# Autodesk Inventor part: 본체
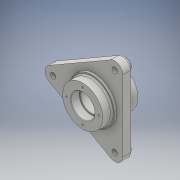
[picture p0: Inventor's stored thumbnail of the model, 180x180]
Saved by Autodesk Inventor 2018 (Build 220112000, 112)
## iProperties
Created: 2023-04
Part Number: 본체
Material: 일반
Document SubType Name: Modeling
Designer: home
Density: 1 g/cm^3
Appearance: 기본값
Author: home
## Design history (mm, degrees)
sketch "스케치1"
  geometry: L1 (82, 0)-(-41, -71.014); L2 (-41, -71.014)-(-41, 71.014); L3 (-41, 71.014)-(82, 0); L4 (90, 13.856)-(-33, 84.87); L5 (-57, 71.014)-(-57, -71.014); L6 (90, -13.856)-(-33, -84.87); A1 r 16 centre (82, 0) between (90, 13.856) and (90, -13.856); A2 r 16 centre (-41, 71.014) between (-33, 84.87) and (-57, 71.014); A3 r 16 centre (-41, -71.014) between (-57, -71.014) and (-33, -84.87); 2 further points
  constraints: 12 end point, 6 point on circle, 6 tangent, 3 centre point, 2 coincident, 1 vertical, 7 other
  dimensions: "d1" = 32 diameter of A1; "d2" = 32 diameter of A2; "d3" = 32 diameter of A3
extrude "돌출1" new body sketch "스케치1" distance "d4" = 18; taper "d5" = 0 deg
sketch "스케치3"
  geometry: L1 (-90, -13.856)-(33, -84.87) reference; L2 (57, -71.014)-(57, 71.014) reference; L3 (33, 84.87)-(-90, 13.856) reference; C1 r 11 at (41, -71.014); C2 r 11 at (41, 71.014); C3 r 11 at (-82, 0); A1 r 16 centre (41, -71.014) between (33, -84.87) and (57, -71.014) reference; A2 r 16 centre (41, 71.014) between (57, 71.014) and (33, 84.87) reference; A3 r 16 centre (-82, 0) between (-90, 13.856) and (-90, -13.856) reference; 1 further point
  constraints: 3 centre point, 3 coincident
  dimensions: "d8" = 22 diameter of C1; "d9" = 22 diameter of C2; "d10" = 22 diameter of C3
extrude "돌출2" join sketch "스케치3" distance "d11" = 4; taper "d12" = 0 deg
hole "구멍1" diameter "d15" = 11; stored, may be unused: countersink angle "d19" = 90 deg, drill point angle "d21" = 118 deg; dims "d13" = 10, "d14" = 10, "d16" = 6, "d17" = 4, "d18" = 2, "d20" = 8
hole "구멍2" diameter "d24" = 11; stored, may be unused: countersink angle "d28" = 90 deg, drill point angle "d30" = 118 deg; dims "d22" = 10, "d23" = 10, "d25" = 6, "d26" = 4, "d27" = 2, "d29" = 8
hole "구멍3" diameter "d33" = 11; stored, may be unused: countersink angle "d37" = 90 deg, drill point angle "d39" = 118 deg; dims "d31" = 10, "d32" = 10, "d34" = 6, "d35" = 4, "d36" = 2, "d38" = 8
sketch "스케치4"
  geometry: C1 r 40 at (0, 0); 1 further point
  constraints: 1 centre point, 1 coincident
  dimensions: "d40" = 80 diameter of C1
extrude "돌출3" join sketch "스케치4" distance "d41" = 29; taper "d42" = 0 deg
sketch "스케치5"
  geometry: C1 r 45 at (0, 0); 1 further point
  constraints: 1 centre point, 1 coincident
  dimensions: "d43" = 90 diameter of C1
extrude "돌출4" join sketch "스케치5" distance "d44" = 5; taper "d45" = 0 deg
sketch "스케치6"
  geometry: C1 r 40 at (0, 0); 1 further point
  constraints: 1 centre point, 1 coincident
  dimensions: "d46" = 80 diameter of C1
extrude "돌출5" join sketch "스케치6" distance "d47" = 18; taper "d48" = 0 deg
hole "구멍4" diameter "d51" = 42; stored, may be unused: countersink angle "d55" = 90 deg, drill point angle "d57" = 118 deg; dims "d49" = 10, "d50" = 10, "d52" = 6, "d53" = 47, "d54" = 17, "d56" = 8
hole "구멍5" diameter "d60" = 42; stored, may be unused: countersink angle "d64" = 90 deg, drill point angle "d66" = 118 deg; dims "d58" = 10, "d59" = 10, "d61" = 6, "d62" = 47, "d63" = 17, "d65" = 8
chamfer "모따기1" distance "d67" = 1; stored, may be unused: second distance "d68" = 2, angle "d69" = 45 deg
fillet "모깎기1" dims "d70" = 0.6
fillet "모깎기2" dims "d71" = 3
fillet "모깎기3" dims "d72" = 3
sketch "스케치7"
  geometry: C1 r 40 at (0, 0) reference; C2 r 24.5 at (0, 0) reference; 2 further points
  dimensions: "d73" = 32 distance of point (0, 0) point (-32, 0)
hole "구멍6" sketch "스케치7" at (-32, 0) diameter "d74" = 3.242; stored, may be unused: countersink angle "d78" = 90 deg, drill point angle "d80" = 118 deg; dims "d75" = 8, "d76" = 47, "d77" = 17, "d79" = 10
fillet "모깎기4" dims "d84" = 3
sketch "스케치8"
  geometry: C1 r 40 at (0, 0) reference; C2 r 24.5 at (0, 0) reference; 2 further points
  dimensions: "d85" = 32 distance of point (0, 0) point (-32, 0)
hole "구멍7" sketch "스케치8" at (-32, 0) diameter "d86" = 3.242; stored, may be unused: countersink angle "d90" = 90 deg, drill point angle "d92" = 118 deg; dims "d87" = 8, "d88" = 47, "d89" = 17, "d91" = 10
sketch "스케치9"
  geometry: 2 further points
  constraints: 1 horizontal alignment, 1 other
  dimensions: "d96" = 60 distance of point (0, 0) point (-60, 0)
feature "엠보싱1" sketch "스케치9" dims "d97" = 0.5, "d98" = 0
node "솔리드1"
pattern_circular "원형 패턴1" dims angle "d82" = 360 deg
pattern_circular "원형 패턴2" dims angle "d94" = 360 deg
node "투영된 루프1"
node "투영된 루프2"
node "투영된 루프3"
